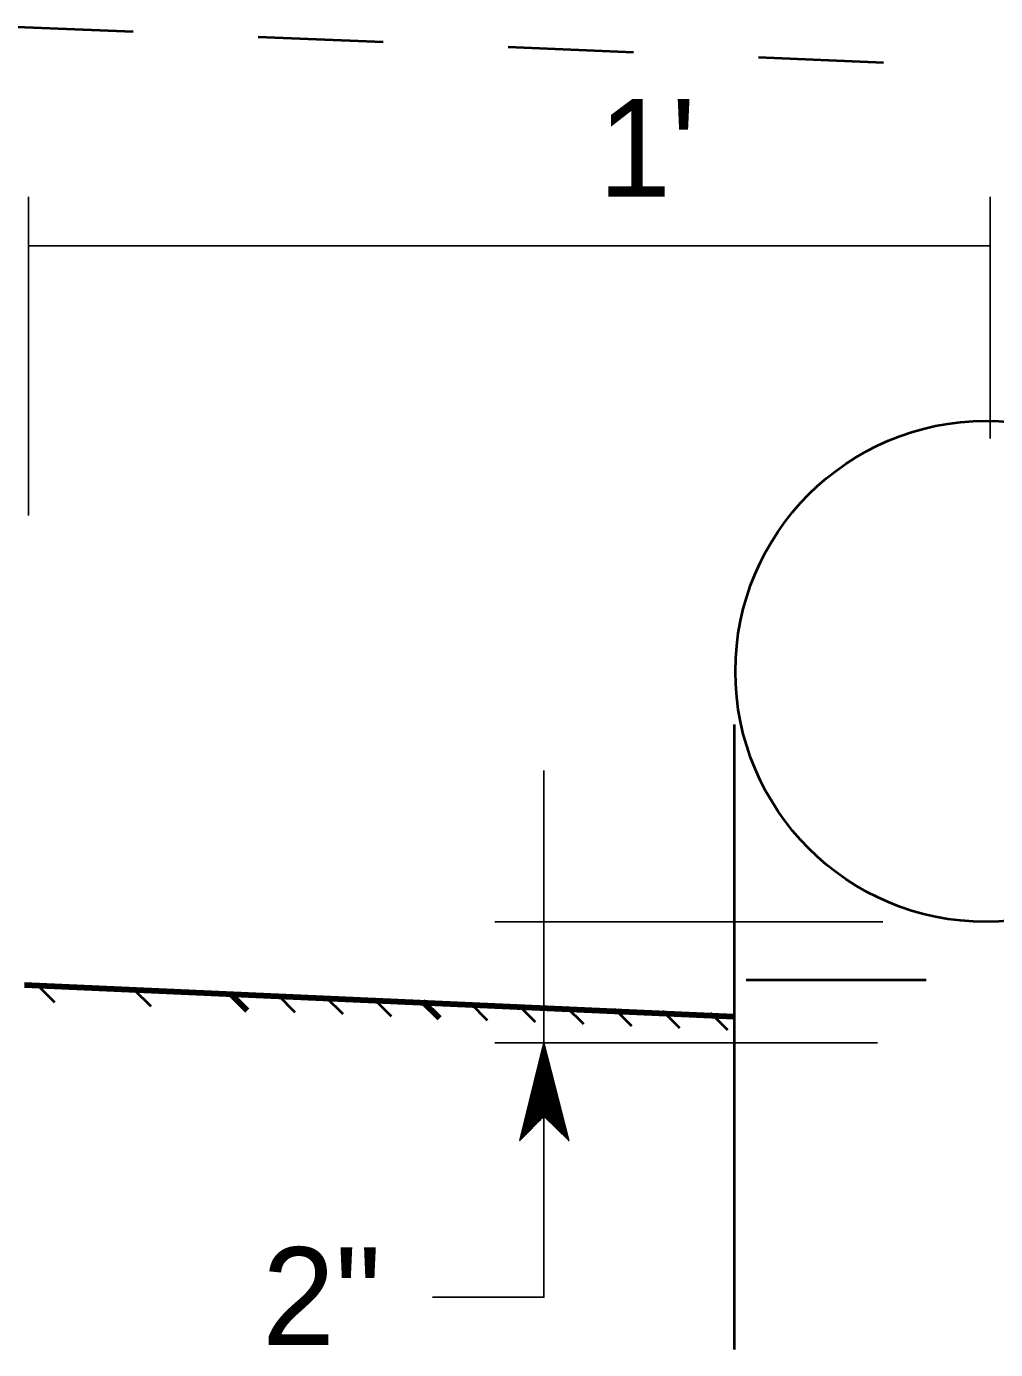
# Model space of a CAD drawing. Extents: x -48732 to -48696.6, y -117659.8 to -117637.8.
# Drawn here: x -48725.536 to -48724.762, y -117657.175 to -117656.117 of the extents above; entities that cross this region are included whole.
import ezdxf

# ---------------------------------------------------------------- set-up
doc = ezdxf.new("R2010")
doc.units = 0
doc.header["$LTSCALE"] = 0.048
doc.linetypes.add('DOTTED', pattern=[1.5, 0.3, -1.2])
doc.linetypes.add('MEDIUM_DASHED', pattern=[4.5, 3, -1.5])
doc.layers.add('11', color=7, linetype='Continuous', lineweight=25)
doc.layers.add('24', color=7, linetype='Continuous', lineweight=40)

msp = doc.modelspace()

# ---------------------------------------------------------------- linework, layer by layer
at = {"layer": '11'}
for p, q in [((-48725.53458, -117656.50825), (-48725.53458, -117656.25358)), ((-48724.76625, -117656.44675), (-48724.76625, -117656.25358)), ((-48724.76625, -117656.29275), (-48725.53458, -117656.29275)), ((-48725.12292, -117656.71217), (-48725.12292, -117657.06667)), ((-48724.85225, -117656.83325), (-48725.16208, -117656.83325)), ((-48724.85625, -117656.92992), (-48725.16208, -117656.92992)), ((-48725.12392, -117656.93375), (-48725.12225, -117656.93258)), ((-48725.12375, -117656.93308), (-48725.12242, -117656.93217)), ((-48725.12358, -117656.93242), (-48725.1225, -117656.93175)), ((-48725.12342, -117656.93175), (-48725.12258, -117656.93125)), ((-48725.12325, -117656.93108), (-48725.12275, -117656.93075)), ((-48725.12308, -117656.9305), (-48725.12292, -117656.93033)), ((-48725.12758, -117656.94858), (-48725.11958, -117656.94308)), ((-48725.12742, -117656.94792), (-48725.11975, -117656.94275)), ((-48725.12725, -117656.94725), (-48725.11983, -117656.94225)), ((-48725.12708, -117656.94658), (-48725.11992, -117656.94175)), ((-48725.12692, -117656.946), (-48725.12008, -117656.94125)), ((-48725.12675, -117656.94542), (-48725.12017, -117656.94092)), ((-48725.12658, -117656.94475), (-48725.12025, -117656.94042)), ((-48725.12642, -117656.94408), (-48725.12042, -117656.93992)), ((-48725.12625, -117656.94342), (-48725.12058, -117656.93942)), ((-48725.12608, -117656.94275), (-48725.12058, -117656.93908)), ((-48725.12592, -117656.94208), (-48725.12075, -117656.93858)), ((-48725.12575, -117656.94142), (-48725.12092, -117656.93808)), ((-48725.12558, -117656.94083), (-48725.12092, -117656.93767)), ((-48725.12542, -117656.94025), (-48725.12108, -117656.93725)), ((-48725.12525, -117656.93958), (-48725.12125, -117656.93675)), ((-48725.12508, -117656.93892), (-48725.12133, -117656.93625)), ((-48725.125, -117656.93825), (-48725.12142, -117656.93583)), ((-48725.12483, -117656.93758), (-48725.12158, -117656.93542)), ((-48725.12475, -117656.93692), (-48725.12175, -117656.93492)), ((-48725.12458, -117656.93625), (-48725.12175, -117656.93442)), ((-48725.12442, -117656.93567), (-48725.12192, -117656.934)), ((-48725.12425, -117656.93508), (-48725.12208, -117656.93358)), ((-48725.12408, -117656.93442), (-48725.12208, -117656.93308)), ((-48725.13133, -117656.96408), (-48725.11675, -117656.95408)), ((-48725.13125, -117656.96342), (-48725.11692, -117656.95367)), ((-48725.13108, -117656.96275), (-48725.11708, -117656.95325)), ((-48725.13092, -117656.96208), (-48725.11708, -117656.95275)), ((-48725.13075, -117656.96142), (-48725.11725, -117656.95225)), ((-48725.13058, -117656.96083), (-48725.11742, -117656.95183)), ((-48725.13042, -117656.96025), (-48725.1175, -117656.95142)), ((-48725.13025, -117656.95958), (-48725.11758, -117656.95092)), ((-48725.13008, -117656.95892), (-48725.11775, -117656.95042)), ((-48725.12992, -117656.95825), (-48725.11792, -117656.95)), ((-48725.12975, -117656.95758), (-48725.11792, -117656.94958)), ((-48725.12958, -117656.95692), (-48725.11808, -117656.94908)), ((-48725.12942, -117656.95633), (-48725.11825, -117656.94858)), ((-48725.12925, -117656.95567), (-48725.11825, -117656.94817)), ((-48725.12908, -117656.95508), (-48725.11842, -117656.94775)), ((-48725.12892, -117656.95442), (-48725.11858, -117656.94725)), ((-48725.12875, -117656.95375), (-48725.11867, -117656.94675)), ((-48725.12858, -117656.95308), (-48725.11875, -117656.94642)), ((-48725.12842, -117656.95242), (-48725.11892, -117656.94592)), ((-48725.12833, -117656.95175), (-48725.11908, -117656.94542)), ((-48725.12817, -117656.95117), (-48725.11908, -117656.94492)), ((-48725.128, -117656.95058), (-48725.11925, -117656.94458)), ((-48725.12792, -117656.94992), (-48725.11942, -117656.94408)), ((-48725.12775, -117656.94925), (-48725.11942, -117656.94358)), ((-48725.13492, -117656.97892), (-48725.11408, -117656.96458)), ((-48725.13483, -117656.97825), (-48725.11425, -117656.96425)), ((-48725.13467, -117656.97758), (-48725.11442, -117656.96375)), ((-48725.13458, -117656.97692), (-48725.11442, -117656.96325)), ((-48725.13442, -117656.97633), (-48725.11458, -117656.96275)), ((-48725.13425, -117656.97575), (-48725.11475, -117656.96242)), ((-48725.13408, -117656.97508), (-48725.11483, -117656.96192)), ((-48725.13392, -117656.97442), (-48725.11492, -117656.96142)), ((-48725.13375, -117656.97375), (-48725.11508, -117656.96092)), ((-48725.13358, -117656.97308), (-48725.11517, -117656.96058)), ((-48725.13342, -117656.97242), (-48725.11525, -117656.96008)), ((-48725.13325, -117656.97175), (-48725.11542, -117656.95958)), ((-48725.13308, -117656.97117), (-48725.11558, -117656.95908)), ((-48725.13292, -117656.97058), (-48725.11558, -117656.95875)), ((-48725.13275, -117656.96992), (-48725.11575, -117656.95825)), ((-48725.13258, -117656.96925), (-48725.11592, -117656.95775)), ((-48725.13242, -117656.96858), (-48725.116, -117656.95733)), ((-48725.13225, -117656.96792), (-48725.11608, -117656.95692)), ((-48725.13208, -117656.96725), (-48725.11625, -117656.95642)), ((-48725.13192, -117656.96658), (-48725.11633, -117656.95592)), ((-48725.13175, -117656.966), (-48725.11642, -117656.9555)), ((-48725.13167, -117656.96542), (-48725.11658, -117656.95508)), ((-48725.1315, -117656.96475), (-48725.11675, -117656.95458)), ((-48725.13858, -117656.99375), (-48725.11142, -117656.97517)), ((-48725.13842, -117656.99308), (-48725.11158, -117656.97475)), ((-48725.13825, -117656.99242), (-48725.11175, -117656.97425)), ((-48725.13817, -117656.99175), (-48725.11175, -117656.97375)), ((-48725.138, -117656.99117), (-48725.11192, -117656.97333)), ((-48725.13783, -117656.99058), (-48725.11208, -117656.97292)), ((-48725.13775, -117656.98992), (-48725.11208, -117656.97242)), ((-48725.13758, -117656.98925), (-48725.11225, -117656.97192)), ((-48725.13742, -117656.98858), (-48725.11242, -117656.9715)), ((-48725.13725, -117656.98792), (-48725.1125, -117656.97108)), ((-48725.13708, -117656.98725), (-48725.11258, -117656.97058)), ((-48725.13692, -117656.98658), (-48725.11275, -117656.97008)), ((-48725.13675, -117656.986), (-48725.11292, -117656.96967)), ((-48725.13658, -117656.98542), (-48725.11292, -117656.96925)), ((-48725.13642, -117656.98475), (-48725.11308, -117656.96875)), ((-48725.13625, -117656.98408), (-48725.11325, -117656.96825)), ((-48725.13608, -117656.98342), (-48725.11325, -117656.96783)), ((-48725.13592, -117656.98275), (-48725.11342, -117656.96742)), ((-48725.13575, -117656.98208), (-48725.11358, -117656.96692)), ((-48725.13558, -117656.9815), (-48725.11367, -117656.96642)), ((-48725.13542, -117656.98083), (-48725.11375, -117656.966)), ((-48725.13525, -117656.98025), (-48725.11392, -117656.96558)), ((-48725.13508, -117656.97958), (-48725.11408, -117656.96508)), ((-48725.14025, -117657.00025), (-48725.11025, -117656.97975)), ((-48725.14008, -117656.99958), (-48725.11042, -117656.97925)), ((-48725.13992, -117656.99892), (-48725.11058, -117656.97875)), ((-48725.13975, -117656.99825), (-48725.11058, -117656.97842)), ((-48725.13958, -117656.99758), (-48725.11075, -117656.97792)), ((-48725.13942, -117656.99692), (-48725.11092, -117656.97742)), ((-48725.13925, -117656.99633), (-48725.111, -117656.97692)), ((-48725.13908, -117656.99575), (-48725.11108, -117656.97658)), ((-48725.13892, -117656.99508), (-48725.11125, -117656.97608)), ((-48725.13875, -117656.99442), (-48725.11133, -117656.97558)), ((-48725.12267, -117656.98875), (-48725.11017, -117656.98025)), ((-48725.12233, -117656.98908), (-48725.11008, -117656.98058)), ((-48725.12208, -117656.98942), (-48725.10992, -117656.98108)), ((-48725.12175, -117656.98975), (-48725.10983, -117656.98158)), ((-48725.12142, -117656.99), (-48725.10975, -117656.98208)), ((-48725.12108, -117656.99025), (-48725.10958, -117656.98242)), ((-48725.12075, -117656.99058), (-48725.10942, -117656.98292)), ((-48725.12042, -117656.99092), (-48725.10942, -117656.98342)), ((-48725.12008, -117656.99125), (-48725.10925, -117656.98392)), ((-48725.11975, -117656.99158), (-48725.10908, -117656.98425)), ((-48725.11942, -117656.99192), (-48725.10908, -117656.98475)), ((-48725.11908, -117656.99225), (-48725.10892, -117656.98525)), ((-48725.11875, -117656.99258), (-48725.10875, -117656.98567)), ((-48725.14108, -117657.00342), (-48725.13042, -117656.99608)), ((-48725.14092, -117657.00275), (-48725.12875, -117656.99442)), ((-48725.14075, -117657.00208), (-48725.12708, -117656.99275)), ((-48725.14058, -117657.0015), (-48725.12542, -117656.99117)), ((-48725.14042, -117657.00092), (-48725.12375, -117656.9895)), ((-48725.11842, -117656.99292), (-48725.10867, -117656.98608)), ((-48725.11817, -117656.99317), (-48725.10858, -117656.98658)), ((-48725.11783, -117656.99342), (-48725.10842, -117656.98708)), ((-48725.11758, -117656.99375), (-48725.10825, -117656.9875)), ((-48725.11725, -117656.99408), (-48725.10825, -117656.98792)), ((-48725.11692, -117656.99442), (-48725.10808, -117656.98842)), ((-48725.11658, -117656.99475), (-48725.10792, -117656.98892)), ((-48725.11625, -117656.99508), (-48725.10792, -117656.98933)), ((-48725.11592, -117656.99542), (-48725.10775, -117656.98975)), ((-48725.11558, -117656.99575), (-48725.10758, -117656.99025)), ((-48725.11525, -117656.99608), (-48725.1075, -117656.99075)), ((-48725.11492, -117656.99633), (-48725.10742, -117656.99117)), ((-48725.11458, -117656.99667), (-48725.10725, -117656.99158)), ((-48725.11425, -117656.99692), (-48725.10708, -117656.99208)), ((-48725.114, -117656.99725), (-48725.10708, -117656.99258)), ((-48725.11367, -117656.99758), (-48725.10692, -117656.993)), ((-48725.11342, -117656.99792), (-48725.10675, -117656.99342)), ((-48725.11308, -117656.99825), (-48725.10675, -117656.99392)), ((-48725.11275, -117656.99858), (-48725.10658, -117656.99442)), ((-48725.11242, -117656.99892), (-48725.10642, -117656.99483)), ((-48725.11208, -117656.99925), (-48725.10633, -117656.99525)), ((-48725.11175, -117656.9995), (-48725.10625, -117656.99575)), ((-48725.11142, -117656.99983), (-48725.10608, -117656.99625)), ((-48725.14192, -117657.00725), (-48725.14025, -117657.00608)), ((-48725.14175, -117657.00667), (-48725.13858, -117657.00442)), ((-48725.14158, -117657.00608), (-48725.13692, -117657.00275)), ((-48725.1415, -117657.00542), (-48725.13525, -117657.00108)), ((-48725.14133, -117657.00475), (-48725.13358, -117656.99942)), ((-48725.14117, -117657.00408), (-48725.132, -117656.99775)), ((-48725.11108, -117657.00008), (-48725.106, -117656.99658)), ((-48725.11075, -117657.00042), (-48725.10592, -117656.99708)), ((-48725.11042, -117657.00075), (-48725.10575, -117656.99758)), ((-48725.11008, -117657.00108), (-48725.10558, -117656.99808)), ((-48725.10975, -117657.00142), (-48725.10558, -117656.99842)), ((-48725.1095, -117657.00175), (-48725.10542, -117656.99892)), ((-48725.10917, -117657.00208), (-48725.10525, -117656.99942)), ((-48725.10892, -117657.00242), (-48725.10517, -117656.99992)), ((-48725.10858, -117657.00275), (-48725.10508, -117657.00025)), ((-48725.10825, -117657.003), (-48725.10492, -117657.00075)), ((-48725.10792, -117657.00325), (-48725.10483, -117657.00125)), ((-48725.10758, -117657.00358), (-48725.10475, -117657.00175)), ((-48725.10725, -117657.00392), (-48725.10458, -117657.00208)), ((-48725.10692, -117657.00425), (-48725.10442, -117657.00258)), ((-48725.10658, -117657.00458), (-48725.10442, -117657.00308)), ((-48725.10625, -117657.00492), (-48725.10425, -117657.0035)), ((-48725.10592, -117657.00525), (-48725.10408, -117657.00392)), ((-48725.10558, -117657.00558), (-48725.10408, -117657.00442)), ((-48725.10525, -117657.00592), (-48725.10392, -117657.00492)), ((-48725.105, -117657.00617), (-48725.10375, -117657.00533)), ((-48725.10475, -117657.0065), (-48725.10367, -117657.00575)), ((-48725.10442, -117657.00675), (-48725.10358, -117657.00625)), ((-48725.10408, -117657.00708), (-48725.10342, -117657.00675)), ((-48725.14208, -117657.00792), (-48725.14192, -117657.00775)), ((-48725.10375, -117657.00742), (-48725.10325, -117657.00717)), ((-48725.10342, -117657.00775), (-48725.10325, -117657.00758))]:
    msp.add_line(p, q, dxfattribs=at)
msp.add_lwpolyline([(-48725.12292, -117656.92992), (-48725.14208, -117657.00808), (-48725.12283, -117656.98858), (-48725.10308, -117657.00808)], close=True, dxfattribs=at)
msp.add_lwpolyline([(-48725.12292, -117657.06667), (-48725.12292, -117657.13325), (-48725.21192, -117657.13325)], dxfattribs=at)
at = {"layer": '24', "linetype": 'DOTTED'}
msp.add_line((-48725.551, -117656.11742), (-48723.96792, -117656.18242), dxfattribs=at)
at = {"layer": '24'}
for p, q in [((-48724.97092, -117656.67542), (-48724.97092, -117657.17508)), ((-48725.51358, -117656.89775), (-48725.52725, -117656.88408)), ((-48725.43675, -117656.90083), (-48725.45042, -117656.88725)), ((-48725.32158, -117656.90558), (-48725.33517, -117656.89192)), ((-48725.28317, -117656.90708), (-48725.29675, -117656.89358)), ((-48725.24475, -117656.90875), (-48725.25842, -117656.89508)), ((-48725.16792, -117656.91192), (-48725.18158, -117656.89825)), ((-48725.12958, -117656.91342), (-48725.14308, -117656.89992)), ((-48725.09108, -117656.91508), (-48725.10475, -117656.90142)), ((-48725.05275, -117656.91658), (-48725.06633, -117656.903)), ((-48725.01433, -117656.91817), (-48725.02792, -117656.90458)), ((-48724.97592, -117656.91975), (-48724.98958, -117656.90617))]:
    msp.add_line(p, q, dxfattribs=at)
at = {"layer": '24', "linetype": 'MEDIUM_DASHED'}
msp.add_line((-48724.57342, -117656.87992), (-48724.97092, -117656.87992), dxfattribs=at)
at = {"layer": '24', "lineweight": 106}
for p, q in [((-48725.53792, -117656.88367), (-48724.97125, -117656.90875)), ((-48725.35992, -117656.904), (-48725.37358, -117656.89042)), ((-48725.20642, -117656.91025), (-48725.21992, -117656.89675))]:
    msp.add_line(p, q, dxfattribs=at)
at = {"layer": '24'}
msp.add_circle((-48724.76964, -117656.633), 0.20026, dxfattribs=at)

# ---------------------------------------------------------------- texts
at = {"layer": '11'}
for s, p in [("  1'", (-48725.13742, -117656.25358)), ('2"', (-48725.34792, -117657.17142))]:
    msp.add_text(s, height=0.07812, dxfattribs=at).set_placement(p)

doc.saveas('drawing.dxf')
